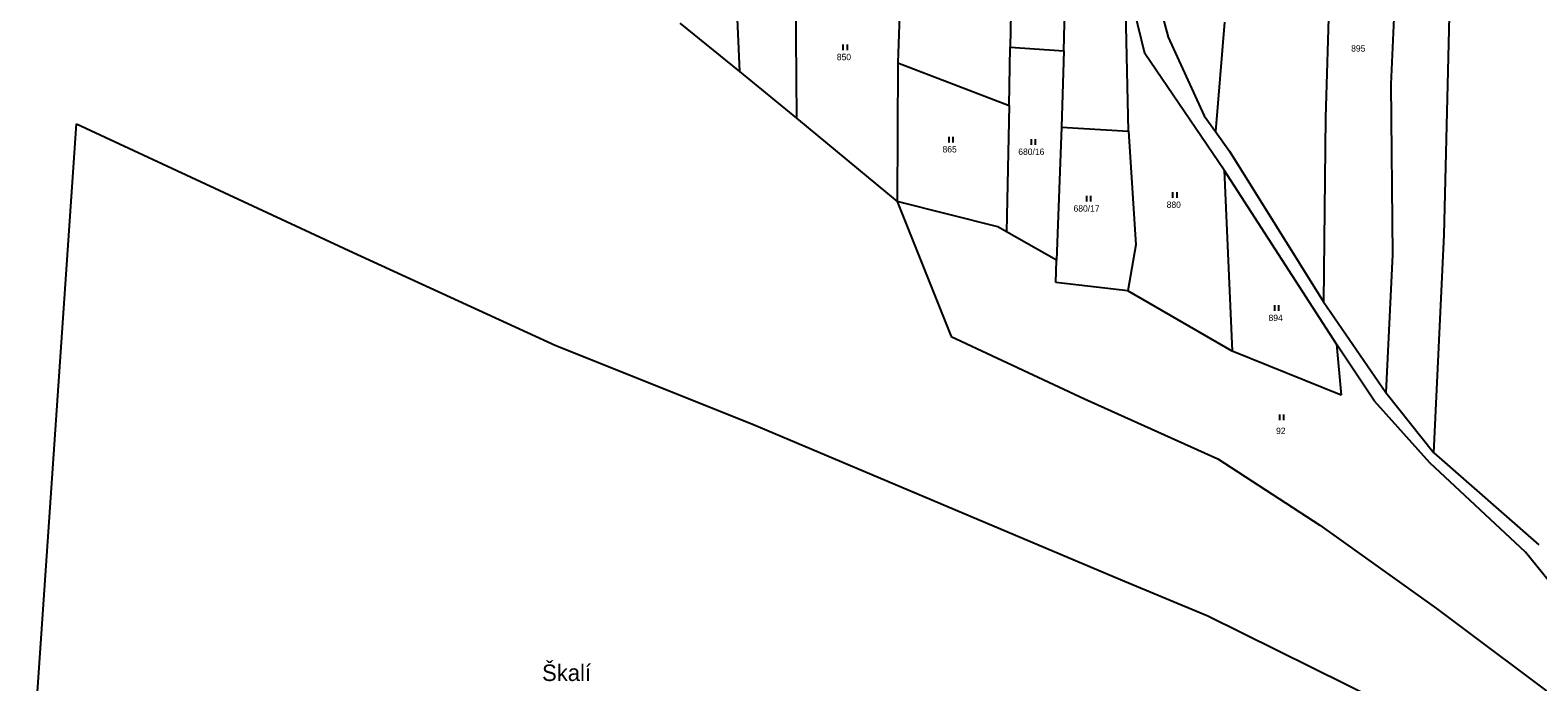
# Model space of a CAD drawing. Extents: x -794142 to -791199, y -1109267 to -1105626.
# Drawn here: x -793043.7 to -792641, y -1108594.9 to -1108421 of the extents above; entities that cross this region are included whole.
import ezdxf

# ---------------------------------------------------------------- set-up
doc = ezdxf.new("R2010")
doc.units = 0
for name, color, linetype in [('Vrstva 1', 7, 'Continuous'), ('Vrstva 14', 7, 'Continuous'), ('Vrstva 23', 7, 'Continuous'), ('Vrstva 39', 7, 'Continuous')]:
    doc.layers.add(name, color=color, linetype=linetype)

msp = doc.modelspace()

# ---------------------------------------------------------------- linework, layer by layer
at = {"layer": 'Vrstva 1'}
for p, q in [((-792780.44, -1108353.88), (-792781.94, -1108425.49)), ((-792767.58, -1108426.45), (-792766.34, -1108377.52)), ((-792839.37, -1108396.76), (-792838.98, -1108444.42)), ((-792855.33, -1108406.24), (-792854.24, -1108432)), ((-792811.1, -1108405.72), (-792811.91, -1108429.71)), ((-792750.3, -1108447.92), (-792751.22, -1108405.47)), ((-792745.94, -1108427.17), (-792751.22, -1108405.47)), ((-792744.34, -1108405.47), (-792739.76, -1108422.84)), ((-792696.65, -1108408.73), (-792697.7, -1108444.29)), ((-792678.93, -1108406.65), (-792680.27, -1108435.34)), ((-792665.97, -1108475.58), (-792664.48, -1108413.59)), ((-792870.21, -1108419.08), (-792854.24, -1108432)), ((-792724.65, -1108418.81), (-792727.1, -1108448.02)), ((-792739.76, -1108422.84), (-792730.13, -1108443.84)), ((-792782.24, -1108441.11), (-792781.94, -1108425.49)), ((-792781.94, -1108425.49), (-792767.58, -1108426.45)), ((-792767.58, -1108426.45), (-792768.21, -1108446.88)), ((-792724.78, -1108458.31), (-792745.94, -1108427.17)), ((-792854.24, -1108432), (-792838.98, -1108444.42)), ((-792811.91, -1108429.71), (-792812.08, -1108466.71)), ((-792811.91, -1108429.71), (-792782.24, -1108441.11)), ((-792680.27, -1108435.34), (-792679.82, -1108480.91)), ((-792838.98, -1108444.42), (-792812.08, -1108466.71)), ((-792782.24, -1108441.11), (-792782.89, -1108474.75)), ((-792730.13, -1108443.84), (-792727.1, -1108448.02)), ((-792697.7, -1108444.29), (-792698.26, -1108493.46)), ((-793043.71, -1108626.34), (-793031.29, -1108445.92)), ((-793031.29, -1108445.92), (-792957.43, -1108480.32)), ((-792768.21, -1108446.88), (-792769.54, -1108482.39)), ((-792768.21, -1108446.88), (-792750.3, -1108447.92)), ((-792750.3, -1108447.92), (-792748.38, -1108478.25)), ((-792727.1, -1108448.02), (-792723.31, -1108453.27)), ((-792723.31, -1108453.27), (-792698.26, -1108493.46)), ((-792724.78, -1108458.31), (-792722.61, -1108506.61)), ((-792694.79, -1108504.73), (-792724.78, -1108458.31)), ((-792785.2, -1108473.43), (-792812.08, -1108466.71)), ((-792812.08, -1108466.71), (-792797.66, -1108502.74)), ((-792782.89, -1108474.75), (-792785.2, -1108473.43)), ((-792769.54, -1108482.39), (-792782.89, -1108474.75)), ((-792668.76, -1108533.79), (-792665.97, -1108475.58)), ((-792957.43, -1108480.32), (-792903.3, -1108505.16)), ((-792748.38, -1108478.25), (-792750.49, -1108490.53)), ((-792679.82, -1108480.91), (-792681.61, -1108517.68)), ((-792769.74, -1108488.29), (-792769.54, -1108482.39)), ((-792750.49, -1108490.53), (-792769.74, -1108488.29)), ((-792722.61, -1108506.61), (-792750.49, -1108490.53)), ((-792698.26, -1108493.46), (-792681.61, -1108517.68)), ((-792903.3, -1108505.16), (-792850.91, -1108526.04)), ((-792797.66, -1108502.74), (-792762.05, -1108519.33)), ((-792684.59, -1108519.95), (-792694.79, -1108504.73)), ((-792694.79, -1108504.73), (-792693.52, -1108518.42)), ((-792693.52, -1108518.42), (-792722.61, -1108506.61)), ((-792762.05, -1108519.33), (-792726.44, -1108535.41)), ((-792669.83, -1108536.49), (-792684.59, -1108519.95)), ((-792681.61, -1108517.68), (-792668.76, -1108533.79)), ((-792850.91, -1108526.04), (-792752.43, -1108567.57)), ((-792726.44, -1108535.41), (-792699.21, -1108553.13)), ((-792644.25, -1108560.28), (-792669.83, -1108536.49)), ((-792668.76, -1108533.79), (-792640.75, -1108558.33)), ((-792699.21, -1108553.13), (-792668.08, -1108575.32)), ((-792630.85, -1108576.94), (-792644.25, -1108560.28)), ((-792752.43, -1108567.57), (-792729.13, -1108577.26)), ((-792729.13, -1108577.26), (-792682.74, -1108600.26)), ((-792668.08, -1108575.32), (-792628.4, -1108605.04))]:
    msp.add_line(p, q, dxfattribs=at)
at = {"layer": 'Vrstva 23'}
for p, q in [((-792826.51, -1108426.27), (-792826.51, -1108424.77)), ((-792825.51, -1108424.77), (-792825.51, -1108426.27)), ((-792798.27, -1108450.9), (-792798.27, -1108449.4)), ((-792797.27, -1108449.4), (-792797.27, -1108450.9)), ((-792776.25, -1108451.56), (-792776.25, -1108450.06)), ((-792775.25, -1108450.06), (-792775.25, -1108451.56)), ((-792761.45, -1108466.69), (-792761.45, -1108465.19)), ((-792760.45, -1108465.19), (-792760.45, -1108466.69)), ((-792738.44, -1108465.7), (-792738.44, -1108464.2)), ((-792737.44, -1108464.2), (-792737.44, -1108465.7)), ((-792711.22, -1108495.9), (-792711.22, -1108494.4)), ((-792710.22, -1108494.4), (-792710.22, -1108495.9)), ((-792709.9, -1108525.09), (-792709.9, -1108523.59)), ((-792708.9, -1108523.59), (-792708.9, -1108525.09))]:
    msp.add_line(p, q, dxfattribs=at)

# ---------------------------------------------------------------- texts
at = {"layer": 'Vrstva 14'}
for s, p in [('895', (-792690.843, -1108426.68)), ('850', (-792828.232, -1108428.97)), ('865', (-792800.003, -1108453.6)), ('680/16', (-792779.762, -1108454.26)), ('680/17', (-792764.999, -1108469.39)), ('880', (-792740.126, -1108468.4)), ('894', (-792712.912, -1108498.6)), ('92', (-792710.907, -1108528.76))]:
    msp.add_text(s, height=1.7, dxfattribs=at).set_placement(p)
at = {"layer": 'Vrstva 39'}
msp.add_text('Škalí', height=4.4, dxfattribs=at).set_placement((-792906.97, -1108594.69))

doc.saveas('drawing.dxf')
